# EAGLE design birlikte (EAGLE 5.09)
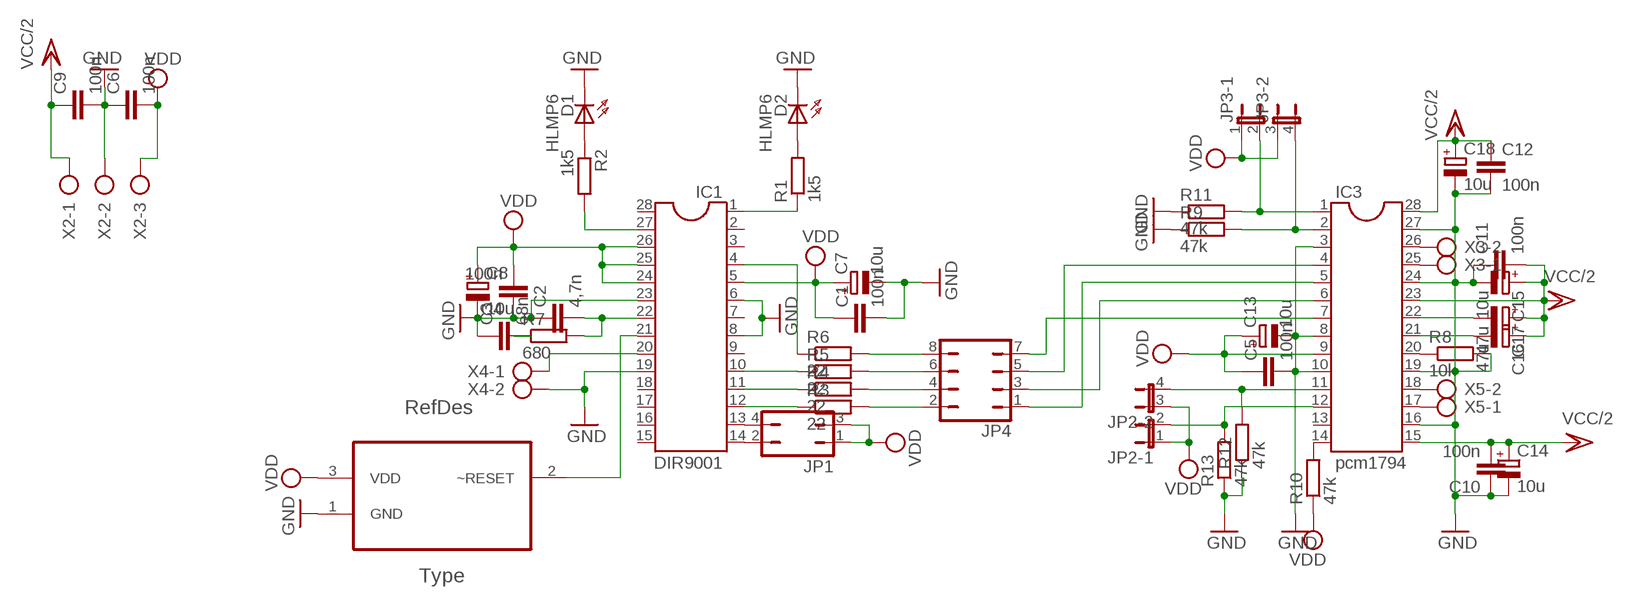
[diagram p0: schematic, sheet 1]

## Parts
C1  100n  C5/2.5  [C5B2.5]
C2  4,7n  C5/2.5  [C5B2.5]
C3  68n  C5/2.5  [C5B2.5]
C4  100n  C5/2.5  [C5B2.5]
C5  100n  C-EU050-030X075  [C050-030X075]
C6  100n  C5/2.5  [C5B2.5]
C7  10u  CPOL-EUTAP5-50  [TAP5-50]
C8  10u  CPOL-EUE5-5  [E5-5]
C9  100n  C5/2.5  [C5B2.5]
C10  100n  C-EU050-030X075  [C050-030X075]
C11  100n  C-EU050-030X075  [C050-030X075]
C12  100n  C-EU050-030X075  [C050-030X075]
C13  10u  CPOL-EUE5-6  [E5-6]
C14  10u  CPOL-EUE5-6  [E5-6]
C15  10u  CPOL-EUE5-6  [E5-6]
C16  47u  CPOL-EUE5-6  [E5-6]
C17  47u  CPOL-EUE5-6  [E5-6]
C18  10u  CPOL-EUE5-6  [E5-6]
D1  HLMP6  [HLMP6]
D2  HLMP6  [HLMP6]
IC1  DIR9001  DIL28  [DIL28-6]
IC3  pcm1794  DIL28  [DIL28-6]
JP1  JP2Q  [JP2Q]
JP2  JP2QE  [JP2Q]
JP3  JP2QE  [JP2Q]
JP4  JP4Q  [JP4Q]
R1  1k5  R-EU_0207/10  [0207/10]
R2  1k5  R-EU_0207/10  [0207/10]
R3  22  R-EU_0207/10  [0207/10]
R4  22  R-EU_0207/10  [0207/10]
R5  22  R-EU_0207/10  [0207/10]
R6  22  R-EU_0207/10  [0207/10]
R7  680  R-EU_0207/10  [0207/10]
R8  10k  R-EU_0207/10  [0207/10]
R9  47k  R-EU_0207/10  [0207/10]
R10  47k  R-EU_0207/10  [0207/10]
R11  47k  R-EU_0207/10  [0207/10]
R12  47k  R-EU_0207/10  [0207/10]
R13  47k  R-EU_0207/10  [0207/10]
U1  TPS3809K33DBVT  [SOT95P280X145-3N]
X2  AK500/3  [AK500/3]
X3  AK500/2  [AK500/2]
X4  AK500/2  [AK500/2]
X5  AK500/2  [AK500/2]

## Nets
GND: C1.2 C2.1 C3.1 C4.1 C5.2 C6.1 C7.- C8.- C9.2 C10.1 C11.1 C12.2 C13.- C14.- C15.- C18.- D1.K D2.K IC1.6 IC1.8 IC1.19 IC1.23 IC3.3 IC3.8 IC3.10 IC3.16 IC3.19 IC3.24 IC3.27 R8.2 R9.1 R11.1 R12.1 R13.1 U1.1(GND) X2.2 X4.2
N$1: IC1.1 R1.1
N$2: IC1.27 R2.2
N$3: IC1.12 R3.1
N$4: IC1.11 R4.1
N$5: IC1.10 R5.1
N$6: IC1.4 R6.1
N$7: IC3.20 R8.1
N$8: IC3.18 X5.2
N$9: IC3.14 R10.2
N$10: IC1.21 U1.2(~RESET)
N$11: IC3.17 X5.1
N$12: C2.2 IC1.22 R7.2
N$13: IC3.26 X3.2
N$14: C3.2 R7.1
N$15: IC3.6 JP4.3
N$16: IC3.4 JP4.5
N$17: IC3.25 X3.1
N$18: IC3.2 JP3.4 R9.2
N$19: D1.A R2.1
N$20: D2.A R1.2
N$21: IC3.7 JP4.7
N$22: IC1.20 X4.1
N$23: IC3.1 JP3.2 R11.2
N$24: JP4.8 R6.2
N$25: IC3.12 JP2.2 R13.2
N$26: IC3.11 JP2.4 R12.2
N$27: JP4.6 R5.2
N$28: IC1.14 JP1.2
N$29: IC1.13 JP1.4
N$30: JP4.4 R4.2
N$31: JP4.2 R3.2
N$33: IC3.5 JP4.1
N$37: C17.- IC3.22
N$38: C16.- IC3.21
VCC/2: C9.1 C10.2 C11.2 C12.1 C14.+ C15.+ C16.+ C17.+ C18.+ IC3.15 IC3.23 IC3.28 X2.1
VDD: C1.1 C4.2 C5.1 C6.2 C7.+ C8.+ C13.+ IC1.5 IC1.24 IC1.25 IC1.26 IC3.9 JP1.1 JP1.3 JP2.1 JP2.3 JP3.1 JP3.3 R10.1 U1.3(VDD) X2.3
Unconnected: IC1.2 IC1.3 IC1.7 IC1.9 IC1.15 IC1.16 IC1.17 IC1.18 IC1.28 IC3.13

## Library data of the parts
C1-C4 C6 C9 = capacitor-wima:C: CAPACITOR
C5 C10-C12 = rcl:C-EU: CAPACITOR, European symbol
C7 C8 = resistor:CPOL-EU: POLARIZED CAPACITOR, European symbol
C13-C18 = rcl:CPOL-EU: POLARIZED CAPACITOR, European symbol
D1 D2 = display-hp:HLMP6: LED
IC1 IC3 = ic-package:DIL28: Dual In Line
JP1 = jumper:JP2Q: JUMPER
JP2 JP3 = jumper:JP2QE: JUMPER
JP4 = jumper:JP4Q: JUMPER
R1-R13 = resistor:R-EU_: RESISTOR, European symbol
U1 = TPS3809K33DB:TPS3809K33DBVT; DESCRIPTION: VOLTAGE SUPERVISORS; MPN: TPS3809K33DBVT; OC_FARNELL: 1103116; OC_NEWARK: 77C0402; PACKAGE: SOT23-3; SUPPLIER: Texas Instruments
X2 = con-ptr500:AK500/3: CONNECTOR
X3-X5 = con-ptr500:AK500/2: CONNECTOR

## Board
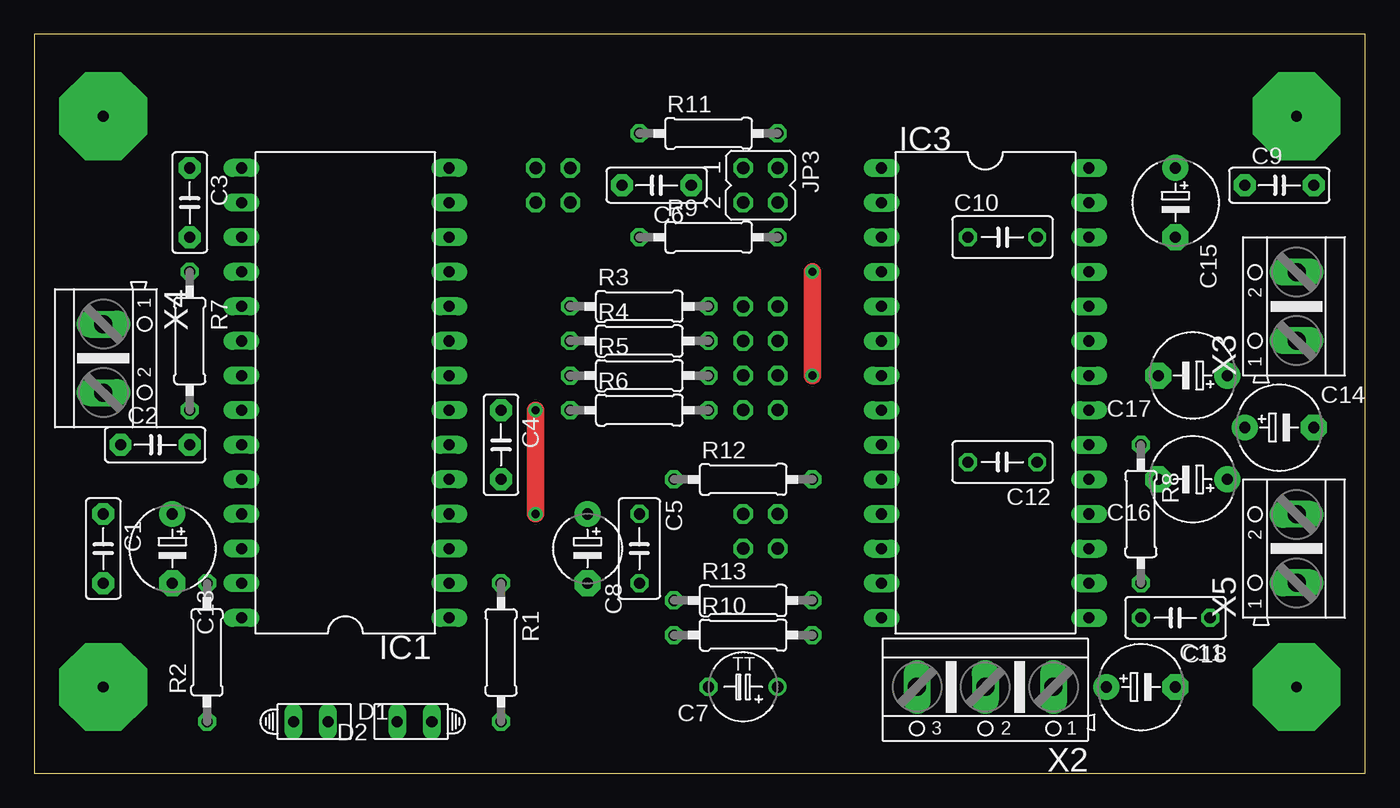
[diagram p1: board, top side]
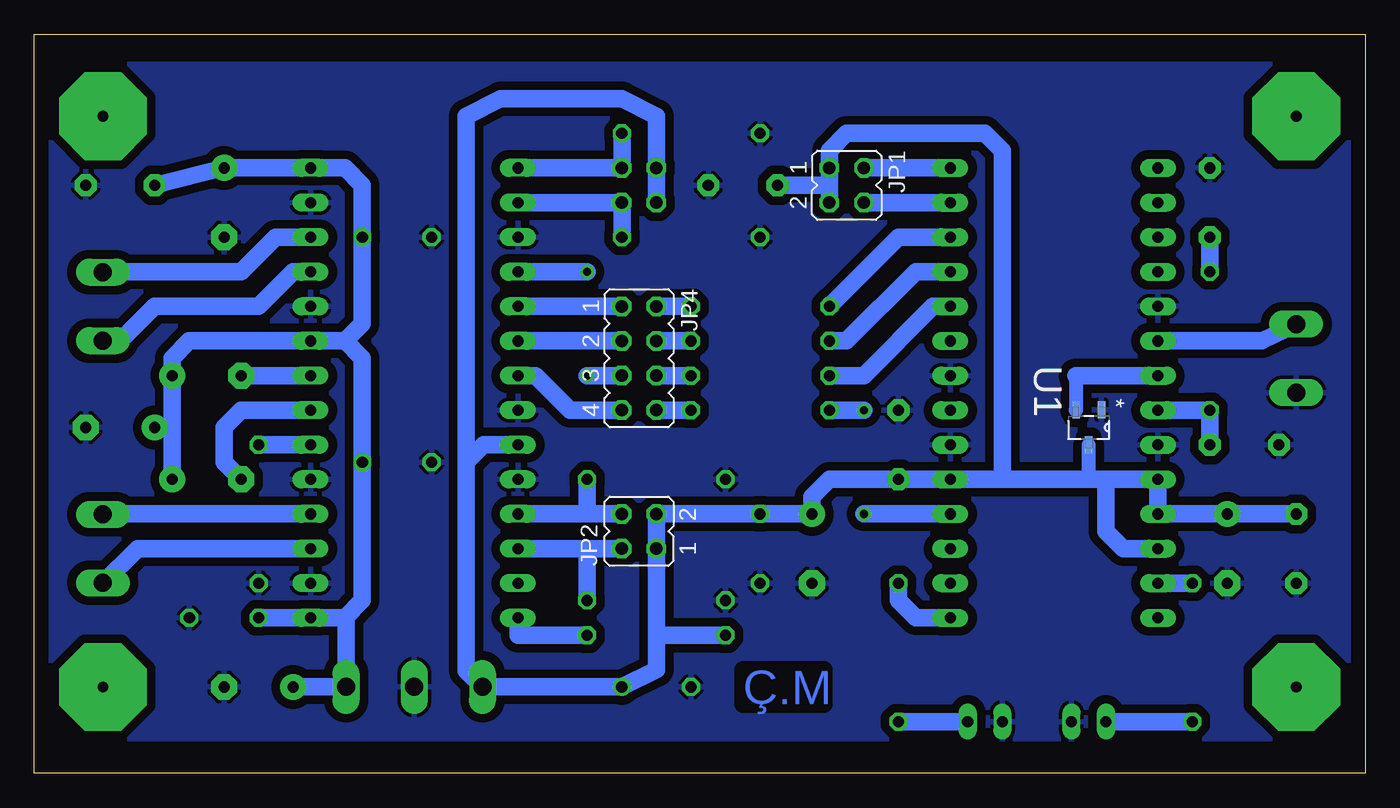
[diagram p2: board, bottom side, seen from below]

Size 97.77 x 54.28 mm. Coordinates in mm from the lower left corner, seen from the top.
Outline: 0,0 97.77,0 97.77,54.28 0,54.28 0,0
Copper layers (1*16): Top 0.035mm / dielectric 1.5mm / Bottom 0.035mm
Design rules "default *": minimum track width 10mil, minimum drill 24mil, track to track 25mil, track to pad 25mil, pad to pad 25mil, via to via 25mil, smd to smd 25mil, copper to edge 40mil, drill to drill 8mil, minimum pad ring 10mil, minimum via ring 8mil, stop-mask expansion 4mil, vias tented up to drill 0mil, thermal gap 10mil

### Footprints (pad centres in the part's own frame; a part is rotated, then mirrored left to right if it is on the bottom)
C5B2.5 = drill 0.813 pad 1.6 octagon: 1 -2.54,0; 2 2.54,0
C050-030X075 = drill 0.813 octagon: 1 -2.54,0; 2 2.54,0
TAP5-50 = drill 0.813 round: + -2.54,0 | drill 0.813 octagon: - 2.54,0
E5-5 = drill 0.813 pad 1.905 round: + -2.54,0 | drill 0.813 pad 1.905 octagon: - 2.54,0
E5-6 = drill 0.813 pad 1.905 round: + -2.54,0 | drill 0.813 pad 1.905 octagon: - 2.54,0
HLMP6 = drill 0.813 long: A -1.27,0; K 1.27,0
DIL28-6 = drill 0.813 long: 1 -16.51,-7.62; 2 -13.97,-7.62; 3 -11.43,-7.62; 4 -8.89,-7.62; 5 -6.35,-7.62; 6 -3.81,-7.62; 7 -1.27,-7.62; 8 1.27,-7.62; 9 3.81,-7.62; 10 6.35,-7.62; 11 8.89,-7.62; 12 11.43,-7.62; 13 13.97,-7.62; 14 16.51,-7.62; 15 16.51,7.62; 16 13.97,7.62; 17 11.43,7.62; 18 8.89,7.62; 19 6.35,7.62; 20 3.81,7.62; 21 1.27,7.62; 22 -1.27,7.62; 23 -3.81,7.62; 24 -6.35,7.62; 25 -8.89,7.62; 26 -11.43,7.62; 27 -13.97,7.62; 28 -16.51,7.62
JP2Q = drill 0.914 octagon: 1 -1.27,-1.27; 2 -1.27,1.27; 3 1.27,-1.27; 4 1.27,1.27
JP4Q = drill 0.914 octagon: 1 -3.81,-1.27; 2 -3.81,1.27; 3 -1.27,-1.27; 4 -1.27,1.27; 5 1.27,-1.27; 6 1.27,1.27; 7 3.81,-1.27; 8 3.81,1.27
0207/10 = drill 0.813 octagon: 1 -5.08,0; 2 5.08,0
SOT95P280X145-3N = smd 1.27 x 0.559: 1 -1.295,0.94; 2 -1.295,-0.94; 3 1.295,0
AK500/3 = drill 1.321 long: 1 -5.004,0; 2 0,0; 3 5.004,0
AK500/2 = drill 1.321 long: 1 -2.515,0; 2 2.515,0

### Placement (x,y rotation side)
C1  5.08,16.51 270 top
C2  8.89,24.13 0 top
C3  11.43,41.91 270 top
C4  34.29,24.13 270 top
C5  44.45,16.51 270 top
C6  45.72,43.18 180 top
C7  52.07,6.35 180 top
C8  40.64,16.51 270 top
C9  91.44,43.18 0 top
C10  71.12,39.37 0 top
C11  83.82,11.43 180 top
C12  71.12,22.86 180 top
C13  10.16,16.51 270 top
C14  91.44,25.4 0 top
C15  83.82,41.91 270 top
C16  85.09,21.59 180 top
C17  85.09,29.21 180 top
C18  81.28,6.35 0 top
D1  20.32,3.81 0 top
D2  27.94,3.81 180 top
IC1  22.86,27.94 90 top
IC3  69.85,27.94 270 top
JP1  38.1,43.18 270 bottom
JP2  53.34,17.78 90 bottom
JP3  53.34,43.18 270 top
JP4  53.34,30.48 270 bottom
R1  34.29,8.89 270 top
R2  12.7,8.89 90 top
R3  44.45,34.29 0 top
R4  44.45,31.75 0 top
R5  44.45,29.21 0 top
R6  44.45,26.67 0 top
R7  11.43,31.75 270 top
R8  81.28,19.05 270 top
R9  49.53,39.37 0 top
R10  52.07,10.16 0 top
R11  49.53,46.99 0 top
R12  52.07,21.59 0 top
R13  52.07,12.7 0 top
U1  20.32,25.4 270 bottom
X2  69.85,6.35 180 top
X3  92.71,34.29 90 top
X4  5.08,30.48 270 top
X5  92.71,16.51 90 top

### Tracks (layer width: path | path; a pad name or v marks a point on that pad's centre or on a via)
GND
  pour Bottom: 1.27,52.07 96.52,52.07 96.52,2.54 1.27,2.54
N$1
  Bottom 1.27: R1.1 34.29,12.7 33.02,11.43 IC1.1
N$2
  Bottom 1.27: R2.2 IC1.27
N$3
  Bottom 1.27: IC1.12 34.29,39.37 R3.1
N$4
  Bottom 1.27: IC1.11 33.02,36.83 38.1,31.75 R4.1
N$5
  Bottom 1.27: IC1.10 31.75,34.29 36.83,29.21 R5.1
N$6  (via drill 0.6)
  Top 1.27: v36.83,19.05 v36.83,26.67
  Bottom 1.27: IC1.4 v36.83,19.05 | v36.83,26.67 R6.1
N$7
  Bottom 1.27: IC3.20 R8.1
N$8
  Bottom 1.27: IC3.18 92.69,19.05 X5.2
N$9
  Bottom 1.27: IC3.14 62.23,10.16 R10.2
N$10
  Bottom 1.016: U1.2 21.27,29.21
  Bottom 1.27: IC1.21 21.27,29.21
N$11
  Bottom 1.27: IC3.17 90.17,16.51 92.71,13.97 92.69,13.97 X5.1
N$12
  Bottom 1.27: IC1.22 R7.2 C2.2
N$13
  Bottom 1.27: IC3.26 80.01,39.37 82.55,36.83 92.69,36.83 X3.2
N$14
  Bottom 1.27: R7.1 C3.2
N$15
  Bottom 1.27: JP4.3 IC3.6
N$16  (via drill 0.6)
  Top 1.27: v57.15,29.21 v57.15,36.83
  Bottom 1.27: JP4.5 v57.15,29.21 | v57.15,36.83 IC3.4
N$17
  Bottom 1.27: IC3.25 78.74,36.83 81.28,34.29 88.9,34.29 91.44,31.75 92.69,31.75 X3.1
N$18
  Bottom 1.27: IC3.2 JP3.4 R9.2
N$19
  Bottom 1.27: R2.1 D1.A
N$20
  Bottom 1.27: D2.A R1.2
N$21
  Bottom 1.27: JP4.7 58.42,26.67 60.96,29.21 IC3.7
N$22
  Bottom 1.27: IC1.20 7.62,31.75 X4.1
N$23
  Bottom 1.27: IC3.1 JP3.2 R11.2
N$24
  Bottom 1.27: R6.2 JP4.8
N$25
  Bottom 1.27: 57.15,16.51 JP2.2 | 57.15,16.51 IC3.12 | R13.2 57.15,16.51
N$26
  Bottom 1.27: JP2.4 57.15,19.05 | 57.15,19.05 IC3.11 | 57.15,19.05 R12.2
N$27
  Bottom 1.27: R5.2 JP4.6
N$28
  Bottom 1.27: IC1.14 JP1.2
N$29
  Bottom 1.27: IC1.13 JP1.4
N$30
  Bottom 1.27: R4.2 JP4.4
N$31
  Bottom 1.27: R3.2 JP4.2
N$32  (via drill 0.8 pad 6.45)
  other vias: 5.08,48.26
N$33
  Bottom 1.27: JP4.1 IC3.5
N$34  (via drill 0.8 pad 6.45)
  other vias: 5.08,6.35
N$35  (via drill 0.8 pad 6.45)
  other vias: 92.71,48.26
N$36  (via drill 0.8 pad 6.45)
  other vias: 92.71,6.35
N$37
  Bottom 1.27: IC3.22 C17.-
N$38
  Bottom 1.27: IC3.21 82.55,26.67 83.82,25.4 83.82,22.86 C16.-
VCC/2
  Bottom 1.27: C11.2 IC3.15 74.93,11.43 | 74.93,31.75 IC3.23 86.36,31.75 87.63,30.48 C17.+ 87.63,25.4 | 74.93,31.75 73.66,33.02 C10.2 73.66,43.18 74.93,44.45 IC3.28 C15.+ C9.1 | 74.93,11.43 73.66,12.7 C12.1 73.66,29.21 73.66,30.48 74.93,31.75 | 87.63,25.4 C16.+ | C18.+ X2.1 74.85,11.35 74.93,11.43 | 87.63,25.4 C14.+
VDD
  Bottom 1.016: 20.32,21.59 U1.3
  Bottom 1.27: 19.05,21.59 IC1.24 IC1.25 C13.+ C1.1 | 19.05,21.59 20.32,21.59 26.67,21.59 | 26.67,21.59 IC1.5 C4.2 39.37,21.59 40.64,20.32 C8.+ C5.1 JP2.3 JP2.1 52.07,10.16 | IC3.9 64.77,24.13 66.04,22.86 | 66.04,22.86 66.04,7.54 X2.3 C7.+ 52.07,7.62 52.07,10.16 | 52.07,10.16 R10.1 | JP3.3 JP3.1 52.07,48.26 54.61,49.53 63.5,49.53 66.04,48.26 66.04,22.86 | 39.37,43.18 JP1.1 39.37,45.72 38.1,46.99 27.94,46.99 26.67,45.72 26.67,21.59 | 39.37,43.18 JP1.3 | IC1.26 17.78,16.51 19.05,17.78 19.05,21.59 | 39.37,43.18 C6.2

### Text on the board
Bottom: Ç.M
